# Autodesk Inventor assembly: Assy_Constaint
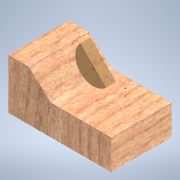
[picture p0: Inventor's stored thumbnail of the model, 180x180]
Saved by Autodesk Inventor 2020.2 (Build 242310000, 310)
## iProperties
Created: 2020-01
Part Number: Assy_Constaint
Document SubType Name: Assembly
Designer: thira
Author: thira
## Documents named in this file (3)
- C:\Users\thira\OneDrive\เดสก์ท็อป\INV-01 Intro to Modeling_2020\Assy_Constraint\Assy_Constaint.iam
- C:\Users\thira\OneDrive\เดสก์ท็อป\INV-01 Intro to Modeling_2020\Assy_Constraint\Main Part.ipt
- C:\Users\thira\OneDrive\เดสก์ท็อป\INV-01 Intro to Modeling_2020\Assy_Constraint\Tangent.ipt
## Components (2 placed, 2 different names)
1. Main Part:1 — Tangent:1, Tangent:2, Angle:1
2. Tangent:1 — Tangent:1, Tangent:2, Angle:1
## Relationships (3: Tangent 2, Angle 1)
- Tangent:1: Main Part:1 ↔ Tangent:1
- Tangent:2: Main Part:1 ↔ Tangent:1
- Angle:1: Main Part:1 ↔ Tangent:1
